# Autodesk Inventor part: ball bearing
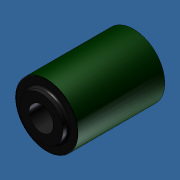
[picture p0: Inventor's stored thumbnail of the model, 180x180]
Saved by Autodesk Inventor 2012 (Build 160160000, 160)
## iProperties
Created: 2010-10
Part Number: ball bearing
Document SubType Name: Modeling
Designer: Administrator
Density: 7.85 g/cm^3
Material: Steel
Mass: 91.3258 g
Surface Area: 41.5127 cm^2
Volume: 11.6339 cm^3
Author: Administrator
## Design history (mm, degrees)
feature "Base1"
body "Solid1"
